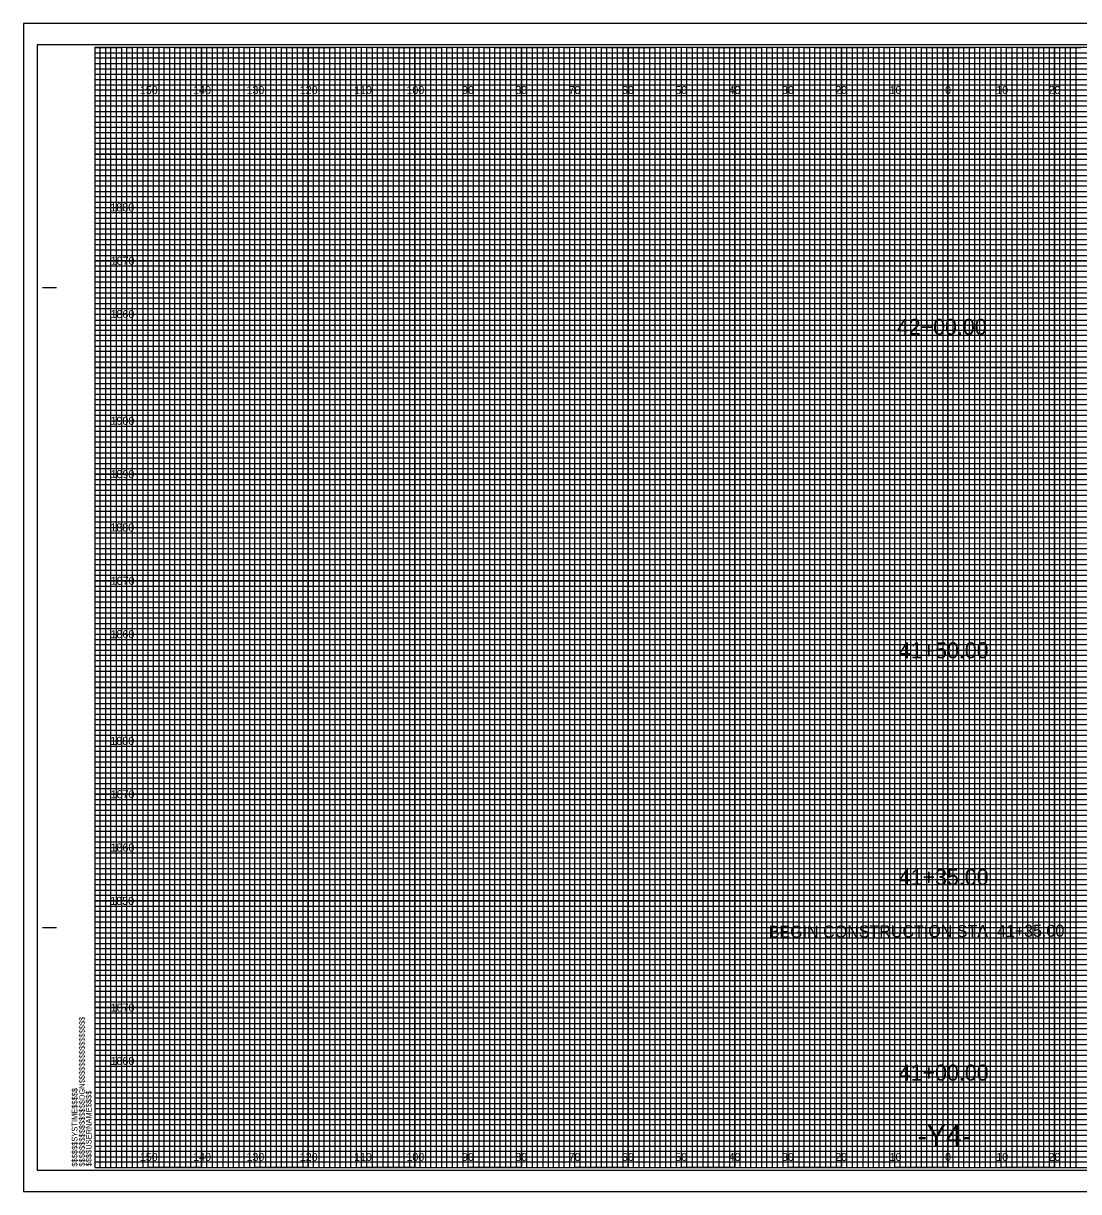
# Model space of a CAD drawing. Extents: x -13 to 323, y -4 to 214.
# Drawn here: x -13.4 to 184.5, y -4.5 to 214.5 of the extents above; entities that cross this region are included whole.
import ezdxf

# ---------------------------------------------------------------- set-up
doc = ezdxf.new("R2010")
doc.units = 0
for name, color, linetype in [('Prop XS Alignment Label', 7, 'Continuous'), ('Prop XS Elevation Labels', 7, 'Continuous'), ('Prop XS Offset Labels', 7, 'Continuous'), ('Prop XS SE Text', 7, 'Continuous'), ('Prop XS Station Labels', 7, 'Continuous'), ('Sheet Cross Section CELL', 7, 'Continuous'), ('Sheet Cross Section Grid Major CELL', 7, 'Continuous'), ('Sheet Cross Section Grid Middle CELL', 7, 'Continuous'), ('Sheet Cross Section Grid Minor 1 CELL', 7, 'Continuous'), ('Sheet Cross Section Grid Minor 2 CELL', 7, 'Continuous'), ('Sheet Cutting Line CELL', 7, 'Continuous'), ('Sheet DOT Grid CELL', 7, 'Continuous'), ('Sheet Plot Border Inside CELL', 7, 'Continuous'), ('Sheet Plot Border Outside CELL', 7, 'Continuous')]:
    doc.layers.add(name, color=color, linetype=linetype)

msp = doc.modelspace()

# ---------------------------------------------------------------- linework, layer by layer
at = {"layer": 'Sheet Cross Section CELL'}
for p, q in [((-9.8, 165), (-7.3, 165)), ((-9.7, 165), (-7.2, 165)), ((-9.8, 45), (-7.3, 45)), ((-9.7, 45), (-7.2, 45))]:
    msp.add_line(p, q, dxfattribs=at)
msp.add_lwpolyline([(320, 210), (0, 210), (0, 0), (320, 0)], close=True, dxfattribs=at)
at = {"layer": 'Sheet Cross Section Grid Major CELL'}
for p, q in [((10, 210), (0, 210)), ((10, 0), (10, 210)), ((30, 210), (20, 210)), ((20, 210), (20, 0)), ((30, 0), (30, 210)), ((50, 210), (40, 210)), ((40, 210), (40, 0)), ((50, 0), (50, 210)), ((70, 210), (60, 210)), ((60, 210), (60, 0)), ((70, 0), (70, 210)), ((90, 210), (80, 210)), ((80, 210), (80, 0)), ((90, 0), (90, 210)), ((110, 210), (100, 210)), ((100, 210), (100, 0)), ((110, 0), (110, 210)), ((130, 210), (120, 210)), ((120, 210), (120, 0)), ((130, 0), (130, 210)), ((150, 210), (140, 210)), ((140, 210), (140, 0)), ((150, 0), (150, 210)), ((170, 210), (160, 210)), ((160, 210), (160, 0)), ((170, 0), (170, 210)), ((190, 210), (180, 210)), ((180, 210), (180, 0)), ((20, 0), (10, 0)), ((40, 0), (30, 0)), ((60, 0), (50, 0)), ((80, 0), (70, 0)), ((100, 0), (90, 0)), ((120, 0), (110, 0)), ((140, 0), (130, 0)), ((160, 0), (150, 0)), ((180, 0), (170, 0))]:
    msp.add_line(p, q, dxfattribs=at)
for points in [[(0, 200), (320, 200), (320, 190), (0, 190)], [(0, 180), (320, 180), (320, 170), (0, 170)], [(0, 160), (320, 160), (320, 150), (0, 150)], [(0, 140), (320, 140), (320, 130), (0, 130)], [(0, 120), (320, 120), (320, 110), (0, 110)], [(0, 100), (320, 100), (320, 90), (0, 90)], [(0, 80), (320, 80), (320, 70), (0, 70)], [(0, 60), (320, 60), (320, 50), (0, 50)], [(0, 40), (320, 40), (320, 30), (0, 30)], [(0, 20), (320, 20), (320, 10), (0, 10)]]:
    msp.add_lwpolyline(points, dxfattribs=at)
at = {"layer": 'Sheet Cross Section Grid Middle CELL'}
for points in [[(0, 210), (5, 210), (5, 0), (15, 0), (15, 210), (25, 210), (25, 0), (35, 0), (35, 210), (45, 210), (45, 0), (55, 0), (55, 210), (65, 210), (65, 0), (75, 0), (75, 210), (85, 210), (85, 0), (95, 0), (95, 210), (105, 210), (105, 0), (115, 0), (115, 210), (125, 210), (125, 0), (135, 0), (135, 210), (145, 210), (145, 0), (155, 0), (155, 210), (165, 210), (165, 0), (175, 0), (175, 210), (185, 210)], [(0, 205), (275, 205)], [(0, 185), (320, 185), (320, 195), (0, 195)], [(0, 165), (320, 165), (320, 175), (0, 175)], [(0, 145), (320, 145), (320, 155), (0, 155)], [(0, 125), (320, 125), (320, 135), (0, 135)], [(0, 105), (320, 105), (320, 115), (0, 115)], [(0, 85), (320, 85), (320, 95), (0, 95)], [(0, 65), (320, 65), (320, 75), (0, 75)], [(0, 45), (320, 45), (320, 55), (0, 55)], [(0, 25), (320, 25), (320, 35), (0, 35)], [(0, 5), (320, 5), (320, 15), (0, 15)]]:
    msp.add_lwpolyline(points, dxfattribs=at)
at = {"layer": 'Sheet Cross Section Grid Minor 1 CELL'}
for p, q in [((0, 209), (260, 209)), ((260, 207.98), (0, 207.98)), ((0, 207.98), (0, 207)), ((0, 207), (260, 207)), ((260, 205.89), (0, 205.89)), ((0, 205.89), (0, 204)), ((0, 204), (320, 204))]:
    msp.add_line(p, q, dxfattribs=at)
for points in [[(0, 203), (270, 203), (320, 203), (320, 202), (0, 202)], [(0, 201), (320, 201), (320, 199), (0, 199)], [(0, 198), (320, 198), (320, 197), (0, 196.98)], [(0, 196), (320, 196), (320, 194), (0, 194)], [(0, 193), (320, 193), (320, 192), (0, 192)], [(0, 191), (320, 191), (320, 189), (0, 189)], [(0, 188), (320, 188), (320, 187), (0, 187)], [(0, 186), (320, 186), (320, 184), (0, 184)], [(0, 183), (320, 183), (320, 182), (0, 182)], [(0, 181), (320, 181), (320, 179), (0, 179)], [(0, 178), (320, 178), (320, 177), (0, 177)], [(0, 176), (320, 176), (320, 173.95), (320, 173), (320, 172), (0, 172)], [(0, 174), (320, 174), (320, 173), (0, 173)], [(0, 171), (320, 171), (320, 169), (0, 169.03)], [(0, 169.03), (320, 169), (320, 168), (0, 168)], [(0, 167), (320, 167), (320, 166), (0, 166)], [(0, 164), (320, 164), (320, 163), (0, 163)], [(0, 162), (320, 162), (320, 161), (0, 161)], [(-0.07, 158.89), (320, 158.89), (320, 157.88), (-0.07, 157.88)], [(0, 157), (320, 157), (320, 156), (0, 156)], [(0, 154), (320, 154), (320, 153), (0, 153)], [(0, 152), (320, 152), (320, 151), (0, 151)], [(0, 149), (320, 149), (320, 148), (0, 148)], [(0, 147), (320, 147), (320, 146), (0, 146)], [(0, 144), (320, 144), (320, 143), (0, 143)], [(0, 142), (320, 142), (320, 141), (0, 141)], [(0, 139), (320, 139), (319.99, 137.98), (0, 138)], [(0, 137), (320, 137), (320, 136), (0, 136)], [(0, 134), (320, 134), (320, 133), (0, 133)], [(0, 132), (320, 132), (320, 131), (0, 131)], [(0, 129), (320, 129), (320, 128), (0, 128)], [(0, 127), (320, 127), (320, 126), (0, 126)], [(0, 124), (320, 124), (320, 123), (0, 123)], [(0, 122), (320, 122), (320, 121), (0, 121)], [(0, 119), (320, 119), (320, 118), (0, 118)], [(0, 116.99), (320.07, 116.91), (320, 116), (0, 116)], [(0, 114), (320, 114), (320, 113), (0, 113)], [(0, 112), (320, 112), (320, 111), (0, 111)], [(0, 109), (320, 109), (320, 108), (0, 108)], [(0, 107), (320, 107), (320, 106), (0, 106)], [(0, 104), (320, 104), (320, 103), (0, 103)], [(0, 102), (320, 102), (320, 101), (0, 101)], [(0, 99), (320, 99), (320, 98), (0, 98)], [(0, 97), (320, 97), (320, 96), (0, 96)], [(0, 94), (320, 94), (320, 93), (0, 93)], [(0, 92), (320, 92), (320, 91), (0, 91)], [(0, 89), (320, 89), (320, 88), (0, 88)], [(0, 87), (320, 87), (320, 86), (0, 86)], [(0, 84), (320, 84), (320, 83), (0, 83)], [(0, 82), (320, 82), (320, 81), (0, 81)], [(0, 79), (320, 79), (319.99, 77.98), (0, 78)], [(0, 77), (320, 77), (320, 76), (0, 76)], [(0, 74), (320, 74), (320, 73), (0, 73)], [(0, 72), (320, 72), (320, 71), (0, 71)], [(0, 69), (320, 69), (320, 68), (0, 68)], [(0, 67), (320, 67), (320, 66), (0, 66)], [(0, 64), (320, 64), (320, 63), (0, 63)], [(0, 62), (320, 62), (320, 61), (0, 61)], [(0, 59), (320, 59), (320, 58), (0, 58)], [(0, 56.99), (320.07, 56.91), (320, 56), (0, 56)], [(0, 54), (320, 54), (320, 53), (0, 53)], [(0, 52), (320, 52), (320, 51), (0, 51)], [(0, 49), (320, 49), (320, 48), (0, 48)], [(0, 47), (320, 47), (320, 46), (0, 46)], [(0, 44), (320, 44), (320, 43), (0, 43)], [(0, 42), (320, 42), (320, 41), (0, 41)], [(0, 39), (320, 39), (320, 38), (0, 38)], [(0, 37), (320, 37), (320, 36), (0, 36)], [(0, 34), (320, 34), (320, 33), (0, 33)], [(0, 32), (320, 32), (320, 31), (0, 31)], [(0, 29), (320, 29), (320, 28), (0, 28)], [(0, 27), (320, 27), (320, 26), (0, 26)], [(0, 24), (320, 24), (320, 23), (0, 23)], [(0, 22), (320, 22), (320, 21), (0, 21)], [(0, 19), (320, 19), (320, 18), (0, 18)], [(0, 17), (320, 17), (320, 16), (0, 16)], [(0, 14), (320, 14), (320, 13), (0, 13)], [(0, 12), (320, 12), (320, 11), (0, 11)], [(0, 9), (320, 9), (320, 8), (0, 8)], [(0, 7), (320, 7), (320, 6), (0, 6)], [(0, 4), (320, 4), (320, 3), (0, 3)], [(0, 2), (320, 2), (320, 1), (0, 1)]]:
    msp.add_lwpolyline(points, dxfattribs=at)
at = {"layer": 'Sheet Cross Section Grid Minor 2 CELL'}
for points in [[(0, 0), (1, 0), (1, 210), (2, 210), (2, 0)], [(2, 0), (3, 0), (3, 210), (4, 210), (4, 0)], [(5, 0), (6, 0), (6, 210), (7, 210), (7, 0)], [(7, 0), (8, 0), (8, 210), (9, 210), (9, 0)], [(10, 0), (11, 0), (11, 210), (12, 210), (12, 0)], [(12, 0), (13, 0), (13, 210), (14, 210), (14, 0)], [(15, 0), (16, 0), (16, 210), (17, 210), (17, 0)], [(17, 0), (18, 0), (18, 210), (19, 210), (19, 0)], [(20, 0), (21, 0), (21, 210), (22, 210), (22, 0)], [(22, 0), (23, 0), (23, 210), (24, 210), (24, 0)], [(25, 0), (26, 0), (26, 210), (27, 210), (27, 0)], [(27, 0), (28, 0), (28, 210), (29, 210), (29, 0)], [(30, 0), (31, 0), (31, 210), (32, 210), (32, 0)], [(32, 0), (33, 0), (33, 210), (34, 210), (34, 0)], [(35, 0), (36, 0), (36, 210), (37, 210), (37, 0)], [(37, 0), (38, 0), (38, 210), (39, 210), (39, 0)], [(40, 0), (41, 0), (41, 210), (42, 210), (42, 0)], [(42, 0), (43, 0), (43, 210), (44, 210), (44, 0)], [(45, 0), (46, 0), (46, 210), (47, 210), (47, 0)], [(47, 0), (48, 0), (48, 210), (49, 210), (49, 0)], [(50, 0), (51, 0), (51, 210), (52, 210), (52, 0)], [(52, 0), (53, 0), (53, 210), (54, 210), (54, 0)], [(55, 0), (56, 0), (56, 210), (57, 210), (57, 0)], [(57, 0), (58, 0), (58, 210), (59, 210), (59, 0)], [(60, 0), (61, 0), (61, 210), (62, 210), (62, 0)], [(62, 0), (63, 0), (63, 210), (64, 210), (64, 0)], [(65, 0), (66, 0), (66, 210), (67, 210), (67, 0)], [(67, 0), (68, 0), (68, 210), (69, 210), (69, 0)], [(70, 0), (71, 0), (71, 210), (72, 210), (72, 0)], [(72, 0), (73, 0), (73, 210), (74, 210), (74, 0)], [(75, 0), (76, 0), (76, 210), (77, 210), (77, 0)], [(77, 0), (78, 0), (78, 210), (79, 210), (79, 0)], [(80, 0), (81, 0), (81, 210), (82, 210), (82, 0)], [(82, 0), (83, 0), (83, 210), (84, 210), (84, 0)], [(85, 0), (86, 0), (86, 210), (87, 210), (87, 0)], [(87, 0), (88, 0), (88, 210), (89, 210), (89, 0)], [(90, 0), (91, 0), (91, 210), (92, 210), (92, 0)], [(92, 0), (93, 0), (93, 210), (94, 210), (94, 0)], [(95, 0), (96, 0), (96, 210), (97, 210), (97, 0)], [(97, 0), (98, 0), (98, 210), (99, 210), (99, 0)], [(100, 0), (101, 0), (101, 210), (102, 210), (102, 0)], [(102, 0), (103, 0), (103, 210), (104, 210), (104, 0)], [(105, 0), (106, 0), (106, 210), (107, 210), (107, 0)], [(107, 0), (108, 0), (108, 210), (109, 210), (109, 0)], [(110, 0), (111, 0), (111, 210), (112, 210), (112, 0)], [(112, 0), (113, 0), (113, 210), (114, 210), (114, 0)], [(115, 0), (116, 0), (116, 210), (117, 210), (117, 0)], [(117, 0), (118, 0), (118, 210), (119, 210), (119, 0)], [(120, 0), (121, 0), (121, 210), (122, 210), (122, 0)], [(122, 0), (123, 0), (123, 210), (124, 210), (124, 0)], [(125, 0), (126, 0), (126, 210), (127, 210), (127, 0)], [(127, 0), (128, 0), (128, 210), (129, 210), (129, 0)], [(130, 0), (131, 0), (131, 210), (132, 210), (132, 0)], [(132, 0), (133, 0), (133, 210), (134, 210), (134, 0)], [(135, 0), (136, 0), (136, 210), (137, 210), (137, 0)], [(137, 0), (138, 0), (138, 210), (139, 210), (139, 0)], [(140, 0), (141, 0), (141, 210), (142, 210), (142, 0)], [(142, 0), (143, 0), (143, 210), (144, 210), (144, 0)], [(145, 0), (146, 0), (146, 210), (147, 210), (147, 0)], [(147, 0), (148, 0), (148, 210), (149, 210), (149, 0)], [(150, 0), (151, 0), (151, 210), (152, 210), (152, 0)], [(152, 0), (153, 0), (153, 210), (154, 210), (154, 0)], [(155, 0), (156, 0), (156, 210), (157, 210), (157, 0)], [(157, 0), (158, 0), (158, 210), (159, 210), (159, 0)], [(160, 0), (161, 0), (161, 210), (162, 210), (162, 0)], [(162, 0), (163, 0), (163, 210), (164, 210), (164, 0)], [(165, 0), (166, 0), (166, 210), (167, 210), (167, 0)], [(167, 0), (168, 0), (168, 210), (169, 210), (169, 0)], [(170, 0), (171, 0), (171, 210), (172, 210), (172, 0)], [(172, 0), (173, 0), (173, 210), (174, 210), (174, 0)], [(175, 0), (176, 0), (176, 210), (177, 210), (177, 0)], [(177, 0), (178, 0), (178, 210), (179, 210), (179, 0)], [(180, 0), (181, 0), (181, 210), (182, 210), (182, 0)], [(182, 0), (183, 0), (183, 210), (184, 210), (184, 0)]]:
    msp.add_lwpolyline(points, dxfattribs=at)
at = {"layer": 'Sheet Cutting Line CELL'}
for p, q in [((323.3, 214.5), (-13.4, 214.5)), ((-13.4, 214.5), (-13.4, -4.5)), ((-13.4, -4.5), (323.3, -4.5))]:
    msp.add_line(p, q, dxfattribs=at)
at = {"layer": 'Sheet DOT Grid CELL'}
for p, q in [((10, 0), (10, 210)), ((20, 0), (20, 210)), ((30, 0), (30, 210)), ((40, 0), (40, 210)), ((50, 0), (50, 210)), ((60, 0), (60, 210)), ((70, 0), (70, 210)), ((80, 0), (80, 210)), ((90, 0), (90, 210)), ((100, 0), (100, 210)), ((110, 0), (110, 210)), ((120, 0), (120, 210)), ((130, 0), (130, 210)), ((140, 0), (140, 210)), ((150, 0), (150, 210)), ((160, 0), (160, 210)), ((170, 0), (170, 210)), ((180, 0), (180, 210)), ((0, 200), (320, 200)), ((0, 190), (320, 190)), ((0, 180), (320, 180)), ((0, 170), (320, 170)), ((0, 160), (320, 160)), ((0, 150), (320, 150)), ((0, 140), (320, 140)), ((0, 130), (320, 130)), ((0, 120), (320, 120)), ((0, 110), (320, 110)), ((0, 100), (320, 100)), ((0, 90), (320, 90)), ((0, 80), (320, 80)), ((0, 70), (320, 70)), ((0, 60), (320, 60)), ((0, 50), (320, 50)), ((0, 40), (320, 40)), ((0, 30), (320, 30)), ((0, 20), (320, 20)), ((0, 10), (320, 10))]:
    msp.add_line(p, q, dxfattribs=at)
at = {"layer": 'Sheet Plot Border Inside CELL'}
msp.add_lwpolyline([(-10.8, -0.5), (322.4, -0.5), (322.4, 210.5), (-10.8, 210.5)], close=True, dxfattribs=at)
at = {"layer": 'Sheet Plot Border Outside CELL'}
msp.add_lwpolyline([(-13.4, -4.5), (323.3, -4.5), (323.3, 214.5), (-13.4, 214.5)], close=True, dxfattribs=at)

# ---------------------------------------------------------------- texts
at = {"layer": 'Prop XS Alignment Label'}
msp.add_text('-Y4-', height=4, dxfattribs=at).set_placement((154.25, 4))
at = {"layer": 'Prop XS Elevation Labels'}
for s, p in [('1880', (2.92, 179.25)), ('1870', (2.98, 169.25)), ('1860', (2.95, 159.25)), ('1900', (2.95, 139.25)), ('1890', (2.95, 129.25)), ('1880', (2.92, 119.25)), ('1870', (2.98, 109.25)), ('1860', (2.95, 99.25)), ('1880', (2.92, 79.25)), ('1870', (2.98, 69.25)), ('1860', (2.95, 59.25)), ('1850', (2.9, 49.25)), ('1870', (2.98, 29.25)), ('1860', (2.95, 19.25))]:
    msp.add_text(s, height=1.5, dxfattribs=at).set_placement(p)
at = {"layer": 'Prop XS Offset Labels'}
for s, p in [('150', (8.44, 201.25)), ('140', (18.44, 201.25)), ('130', (28.44, 201.25)), ('120', (38.44, 201.25)), ('110', (48.62, 201.25)), ('100', (58.44, 201.25)), ('90', (68.86, 201.25)), ('80', (78.86, 201.25)), ('70', (88.86, 201.25)), ('60', (98.86, 201.25)), ('50', (108.86, 201.25)), ('40', (118.86, 201.25)), ('30', (128.86, 201.25)), ('20', (138.86, 201.25)), ('10', (149.04, 201.25)), ('0', (159.45, 201.25)), ('0', (159.45, 201.25)), ('10', (169.04, 201.25)), ('20', (178.86, 201.25)), ('150', (8.44, 1.25)), ('140', (18.44, 1.25)), ('130', (28.44, 1.25)), ('120', (38.44, 1.25)), ('110', (48.62, 1.25)), ('100', (58.44, 1.25)), ('90', (68.86, 1.25)), ('80', (78.86, 1.25)), ('70', (88.86, 1.25)), ('60', (98.86, 1.25)), ('50', (108.86, 1.25)), ('40', (118.86, 1.25)), ('30', (128.86, 1.25)), ('20', (138.86, 1.25)), ('10', (149.04, 1.25)), ('0', (159.45, 1.25)), ('0', (159.45, 1.25)), ('10', (169.04, 1.25)), ('20', (178.86, 1.25))]:
    msp.add_text(s, height=1.5, dxfattribs=at).set_placement(p)
at = {"layer": 'Prop XS SE Text'}
msp.add_text('BEGIN CONSTRUCTION STA. 41+35.00', height=2.25, rotation=0.2093, dxfattribs=at).set_placement((126.39, 43.09))
at = {"layer": 'Prop XS Station Labels'}
for s, p in [('42+00.00', (150.41, 156.11)), ('41+50.00', (150.77, 95.48)), ('41+35.00', (150.77, 52.97)), ('41+00.00', (150.77, 16.31))]:
    msp.add_text(s, height=3, dxfattribs=at).set_placement(p)
at = {"layer": 'Sheet Cross Section CELL'}
for s, p in [('$$$$$$$$$$$$$$$$DGN$$$$$$$$$$$$$$$$', (-1.88, 0.18)), ('$$$$$$SYSTIME$$$$$', (-3.26, 0.18)), ('$$$$USERNAME$$$$', (-0.62, 0.23))]:
    msp.add_text(s, height=1.05, rotation=90, dxfattribs=at).set_placement(p)

doc.saveas('drawing.dxf')
